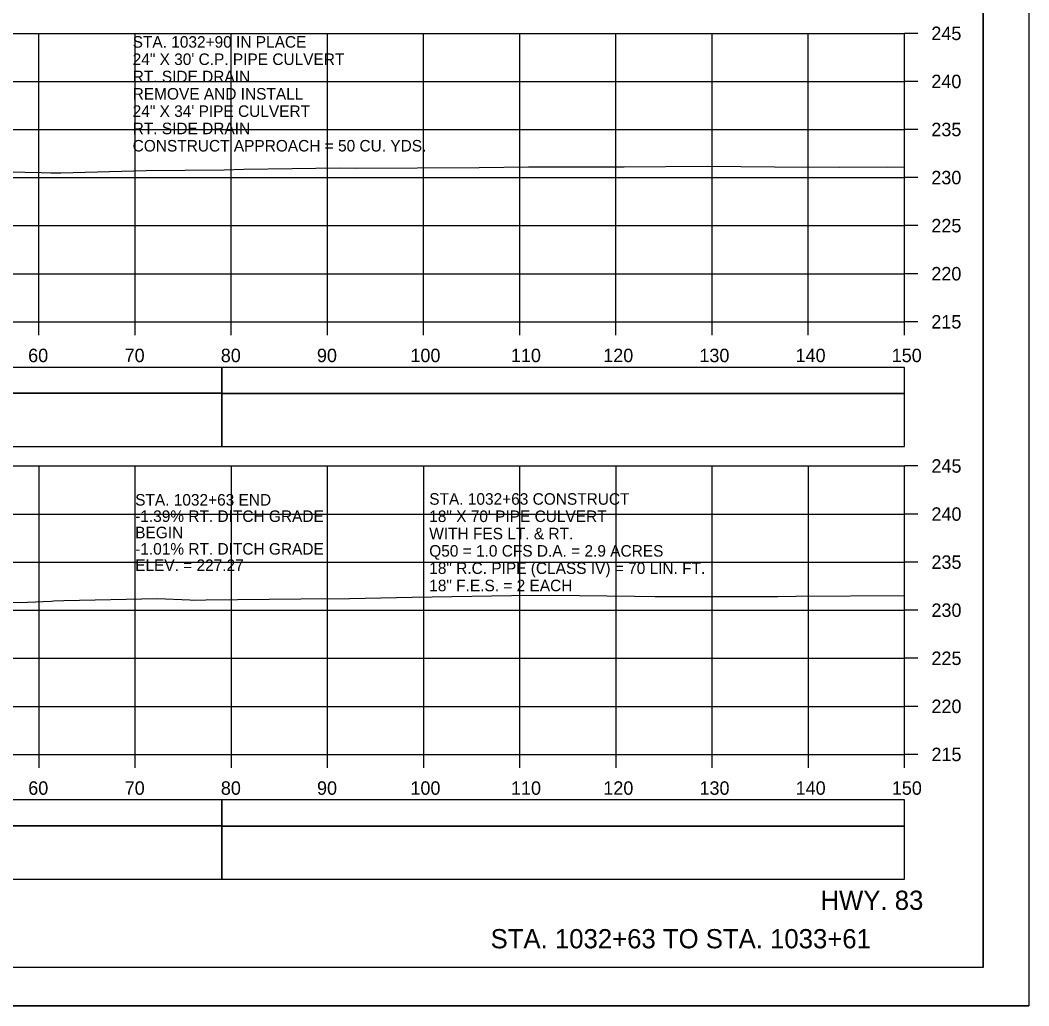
# Model space of a CAD drawing. Extents: x 1386544 to 1388153, y 379785 to 390999.
# Drawn here: x 1387417.7 to 1387522.6, y 385878.8 to 385981.4 of the extents above; entities that cross this region are included whole.
import ezdxf

# ---------------------------------------------------------------- set-up
doc = ezdxf.new("R2010")
doc.units = 0
for name, color, linetype in [('R_Axis', 7, 'Continuous'), ('R_Axis Annot', 7, 'Continuous'), ('R_Border', 7, 'Continuous'), ('R_Draft', 7, 'Continuous'), ('R_Drive', 7, 'Continuous'), ('R_Exist Surface', 7, 'Continuous'), ('R_Fin Surface Annot', 7, 'Continuous'), ('R_Grid', 7, 'Continuous'), ('R_No Plot', 7, 'Continuous'), ('R_Striping', 7, 'Continuous'), ('R_Water Annot', 7, 'Continuous')]:
    doc.layers.add(name, color=color, linetype=linetype)

msp = doc.modelspace()

# ---------------------------------------------------------------- linework, layer by layer
at = {"layer": 'R_Axis'}
for p, q in [((1387509.67, 385949.98), (1387509.67, 385979.98)), ((1387511.07, 385979.98), (1387509.67, 385979.98)), ((1387511.07, 385974.98), (1387509.67, 385974.98)), ((1387511.07, 385969.98), (1387509.67, 385969.98)), ((1387511.07, 385964.98), (1387509.67, 385964.98)), ((1387511.07, 385959.98), (1387509.67, 385959.98)), ((1387511.07, 385954.98), (1387509.67, 385954.98)), ((1387209.67, 385949.98), (1387509.67, 385949.98)), ((1387419.67, 385948.58), (1387419.67, 385949.98)), ((1387429.67, 385948.58), (1387429.67, 385949.98)), ((1387439.67, 385948.58), (1387439.67, 385949.98)), ((1387449.67, 385948.58), (1387449.67, 385949.98)), ((1387459.67, 385948.58), (1387459.67, 385949.98)), ((1387469.67, 385948.58), (1387469.67, 385949.98)), ((1387479.67, 385948.58), (1387479.67, 385949.98)), ((1387489.67, 385948.58), (1387489.67, 385949.98)), ((1387499.67, 385948.58), (1387499.67, 385949.98)), ((1387509.67, 385948.58), (1387509.67, 385949.98)), ((1387511.07, 385949.98), (1387509.67, 385949.98)), ((1387509.68, 385904.98), (1387509.68, 385934.98)), ((1387511.08, 385934.98), (1387509.68, 385934.98)), ((1387511.08, 385929.98), (1387509.68, 385929.98)), ((1387511.08, 385924.98), (1387509.68, 385924.98)), ((1387511.08, 385919.98), (1387509.68, 385919.98)), ((1387511.08, 385914.98), (1387509.68, 385914.98)), ((1387511.08, 385909.98), (1387509.68, 385909.98)), ((1387209.68, 385904.98), (1387509.68, 385904.98)), ((1387419.68, 385903.58), (1387419.68, 385904.98)), ((1387429.68, 385903.58), (1387429.68, 385904.98)), ((1387439.68, 385903.58), (1387439.68, 385904.98)), ((1387449.68, 385903.58), (1387449.68, 385904.98)), ((1387459.68, 385903.58), (1387459.68, 385904.98)), ((1387469.68, 385903.58), (1387469.68, 385904.98)), ((1387479.68, 385903.58), (1387479.68, 385904.98)), ((1387489.68, 385903.58), (1387489.68, 385904.98)), ((1387499.68, 385903.58), (1387499.68, 385904.98)), ((1387509.68, 385903.58), (1387509.68, 385904.98)), ((1387511.08, 385904.98), (1387509.68, 385904.98))]:
    msp.add_line(p, q, dxfattribs=at)
at = {"layer": 'R_Axis Annot'}
for points in [[(1387438.7, 385942.53), (1387509.68, 385942.53), (1387509.68, 385945.24), (1387438.7, 385945.24)], [(1387438.7, 385937.01), (1387509.68, 385937.01), (1387509.68, 385942.53), (1387438.7, 385942.53)], [(1387438.7, 385897.53), (1387509.68, 385897.53), (1387509.68, 385900.24), (1387438.7, 385900.24)], [(1387438.7, 385892.01), (1387509.68, 385892.01), (1387509.68, 385897.53), (1387438.7, 385897.53)]]:
    msp.add_lwpolyline(points, close=True, dxfattribs=at)
at = {"layer": 'R_Border'}
for q in [(1387517.86, 386088.27), (1387201.68, 385882.81)]:
    msp.add_line((1387517.86, 385882.81), q, dxfattribs=at)
at = {"layer": 'R_Exist Surface'}
for points in [[(1387416.52, 385965.59), (1387419.91, 385965.52), (1387420.91, 385965.47), (1387421.96, 385965.48), (1387430.81, 385965.73), (1387438.92, 385965.8), (1387440.99, 385965.84), (1387446.01, 385965.91), (1387450.94, 385965.98), (1387452.58, 385965.97), (1387465.45, 385966.01), (1387470.57, 385966.08), (1387480.54, 385966.1), (1387489.16, 385966.16), (1387496.16, 385966.08), (1387502.97, 385966.06), (1387507.88, 385966.1), (1387509.67, 385966.07)], [(1387410.18, 385920.77), (1387418.48, 385920.82), (1387420.93, 385920.92), (1387421.22, 385920.94), (1387422.25, 385920.98), (1387432.01, 385921.2), (1387435.38, 385921.06), (1387435.75, 385921.03), (1387437.02, 385921.05), (1387446.91, 385921.17), (1387451.96, 385921.18), (1387458.49, 385921.35), (1387468.82, 385921.52), (1387473.02, 385921.56), (1387481.59, 385921.43), (1387483.74, 385921.41), (1387496.46, 385921.42), (1387498.41, 385921.43), (1387509.68, 385921.5)]]:
    msp.add_lwpolyline(points, dxfattribs=at)
at = {"layer": 'R_Grid'}
for p, q in [((1387209.67, 385979.98), (1387509.67, 385979.98)), ((1387419.67, 385949.98), (1387419.67, 385979.98)), ((1387429.67, 385949.98), (1387429.67, 385979.98)), ((1387439.67, 385949.98), (1387439.67, 385979.98)), ((1387449.67, 385949.98), (1387449.67, 385979.98)), ((1387459.67, 385949.98), (1387459.67, 385979.98)), ((1387469.67, 385949.98), (1387469.67, 385979.98)), ((1387479.67, 385949.98), (1387479.67, 385979.98)), ((1387489.67, 385949.98), (1387489.67, 385979.98)), ((1387499.67, 385949.98), (1387499.67, 385979.98)), ((1387509.67, 385949.98), (1387509.67, 385979.98)), ((1387209.67, 385974.98), (1387509.67, 385974.98)), ((1387209.67, 385969.98), (1387509.67, 385969.98)), ((1387209.67, 385964.98), (1387509.67, 385964.98)), ((1387209.67, 385959.98), (1387509.67, 385959.98)), ((1387209.67, 385954.98), (1387509.67, 385954.98)), ((1387209.67, 385949.98), (1387509.67, 385949.98)), ((1387209.68, 385934.98), (1387509.68, 385934.98)), ((1387419.68, 385904.98), (1387419.68, 385934.98)), ((1387429.68, 385904.98), (1387429.68, 385934.98)), ((1387439.68, 385904.98), (1387439.68, 385934.98)), ((1387449.68, 385904.98), (1387449.68, 385934.98)), ((1387459.68, 385904.98), (1387459.68, 385934.98)), ((1387469.68, 385904.98), (1387469.68, 385934.98)), ((1387479.68, 385904.98), (1387479.68, 385934.98)), ((1387489.68, 385904.98), (1387489.68, 385934.98)), ((1387499.68, 385904.98), (1387499.68, 385934.98)), ((1387509.68, 385904.98), (1387509.68, 385934.98)), ((1387209.68, 385929.98), (1387509.68, 385929.98)), ((1387209.68, 385924.98), (1387509.68, 385924.98)), ((1387209.68, 385919.98), (1387509.68, 385919.98)), ((1387209.68, 385914.98), (1387509.68, 385914.98)), ((1387209.68, 385909.98), (1387509.68, 385909.98)), ((1387209.68, 385904.98), (1387509.68, 385904.98))]:
    msp.add_line(p, q, dxfattribs=at)
at = {"layer": 'R_No Plot'}
msp.add_line((1387189.28, 385878.83), (1387522.61, 385878.83), dxfattribs=at)
for points in [[(1387189.27, 386092.17), (1387522.61, 386092.17), (1387522.61, 385878.83), (1387189.27, 385878.83)], [(1387435.6, 386088.27), (1387455.22, 386088.27), (1387455.22, 386078.39), (1387471.33, 386078.39), (1387494.53, 386078.39), (1387494.53, 386054.06), (1387517.86, 386054.06), (1387517.86, 385882.81), (1387201.68, 385882.81), (1387201.68, 386088.27)]]:
    msp.add_lwpolyline(points, close=True, dxfattribs=at)
at = {"layer": 'R_Striping'}
for points in [[(1387407.36, 385942.54), (1387438.7, 385942.54), (1387438.7, 385945.24), (1387407.36, 385945.24)], [(1387407.36, 385937.01), (1387438.7, 385937.01), (1387438.7, 385942.54), (1387407.36, 385942.54)], [(1387407.36, 385897.54), (1387438.7, 385897.54), (1387438.7, 385900.24), (1387407.36, 385900.24)], [(1387407.36, 385892.01), (1387438.7, 385892.01), (1387438.7, 385897.54), (1387407.36, 385897.54)]]:
    msp.add_lwpolyline(points, close=True, dxfattribs=at)

# ---------------------------------------------------------------- texts
at = {"layer": 'R_Axis Annot'}
for s, p in [('245', (1387512.47, 385979.28)), ('240', (1387512.47, 385974.28)), ('235', (1387512.47, 385969.28)), ('230', (1387512.47, 385964.28)), ('225', (1387512.47, 385959.28)), ('220', (1387512.47, 385954.28)), ('215', (1387512.47, 385949.28)), ('60', (1387418.55, 385945.78)), ('70', (1387428.58, 385945.78)), ('80', (1387438.58, 385945.78)), ('90', (1387448.58, 385945.78)), ('100', (1387458.3, 385945.78)), ('110', (1387468.75, 385945.78)), ('120', (1387478.35, 385945.78)), ('130', (1387488.35, 385945.78)), ('140', (1387498.35, 385945.78)), ('150', (1387508.35, 385945.78)), ('245', (1387512.48, 385934.28)), ('240', (1387512.48, 385929.28)), ('235', (1387512.48, 385924.28)), ('230', (1387512.48, 385919.28)), ('225', (1387512.48, 385914.28)), ('220', (1387512.48, 385909.28)), ('215', (1387512.48, 385904.28)), ('60', (1387418.56, 385900.78)), ('70', (1387428.59, 385900.78)), ('80', (1387438.59, 385900.78)), ('90', (1387448.59, 385900.78)), ('100', (1387458.3, 385900.78)), ('110', (1387468.76, 385900.78)), ('120', (1387478.36, 385900.78)), ('130', (1387488.36, 385900.78)), ('140', (1387498.36, 385900.78)), ('150', (1387508.36, 385900.78))]:
    msp.add_text(s, height=1.4, dxfattribs=at).set_placement(p)
at = {"layer": 'R_Draft'}
for s, p in [('HWY. 83', (1387500.94, 385888.81)), ('STA. 1032+63 TO STA. 1033+61', (1387466.64, 385884.81))]:
    msp.add_text(s, height=2, dxfattribs=at).set_placement(p)
at = {"layer": 'R_Drive'}
for s, p in [('STA. 1032+90 IN PLACE', (1387429.42, 385978.49)), ('24" X 30\' C.P. PIPE CULVERT', (1387429.42, 385976.69)), ('RT. SIDE DRAIN', (1387429.42, 385974.89)), ('REMOVE AND INSTALL', (1387429.42, 385973.09)), ('24" X 34\' PIPE CULVERT', (1387429.42, 385971.29)), ('RT. SIDE DRAIN', (1387429.42, 385969.49)), ('CONSTRUCT APPROACH = 50 CU. YDS.', (1387429.42, 385967.69))]:
    msp.add_text(s, height=1.2, dxfattribs=at).set_placement(p)
at = {"layer": 'R_Fin Surface Annot'}
for s, p in [('STA. 1032+63 END', (1387429.68, 385930.86)), ('-1.39% RT. DITCH GRADE', (1387429.68, 385929.16)), ('BEGIN', (1387429.68, 385927.46)), ('-1.01% RT. DITCH GRADE', (1387429.68, 385925.76)), ('ELEV. = 227.27', (1387429.68, 385924.06))]:
    msp.add_text(s, height=1.2, dxfattribs=at).set_placement(p)
at = {"layer": 'R_Water Annot'}
for s, p in [('STA. 1032+63 CONSTRUCT', (1387460.26, 385930.95)), ('18" X 70\' PIPE CULVERT', (1387460.26, 385929.15)), ('WITH FES LT. & RT.', (1387460.26, 385927.35)), ('Q50 = 1.0 CFS D.A. = 2.9 ACRES', (1387460.26, 385925.55)), ('18" R.C. PIPE (CLASS IV) = 70 LIN. FT.', (1387460.26, 385923.75)), ('18" F.E.S. = 2 EACH', (1387460.26, 385921.95))]:
    msp.add_text(s, height=1.2, dxfattribs=at).set_placement(p)

doc.saveas('drawing.dxf')
